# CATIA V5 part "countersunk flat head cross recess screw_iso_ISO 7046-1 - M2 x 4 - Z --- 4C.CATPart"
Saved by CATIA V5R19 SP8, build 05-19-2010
Part number: countersunk flat head cross recess screw_iso_ISO 7046-1 - M2 x 4 - Z --- 4C
Revision: ANY
Definition: UNKNOWN
Nomenclature: countersunk flat head cross recess screw_iso_ISO 7046-1 - M2 x 4 - Z --- 4C
Source: Unknown
Bounding box of the stored display mesh (mm): x 0 to 4, y -1.9 to 1.9, z -1.9 to 1.9
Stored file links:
  D:\Documents\1_Travail\1 - ac-limoges.fr\ac-limoges.fr\Emmanuel Maynard - STI2D_Turgot\2 -2I2D\2_SEQUENCE_Serrure_Biométrique\5-Spé_ITEC\Serrure_Bio_Eleve\countersunk flat head cross recess screw_iso_ISO 7046-1 - M2 x 4 - Z --- 4C.CATPart
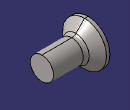
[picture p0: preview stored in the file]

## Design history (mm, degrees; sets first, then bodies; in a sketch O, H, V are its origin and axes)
Body1 "RecessCore" (main body)
  Solid1: solid without history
